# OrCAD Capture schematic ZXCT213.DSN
size C; title: ZXCT213, 26V, ZERO-DRIFT, HIGH PRECISION CURRENT MONITOR; rev: 1.0; note: DS45449 Rev. 2 - 2
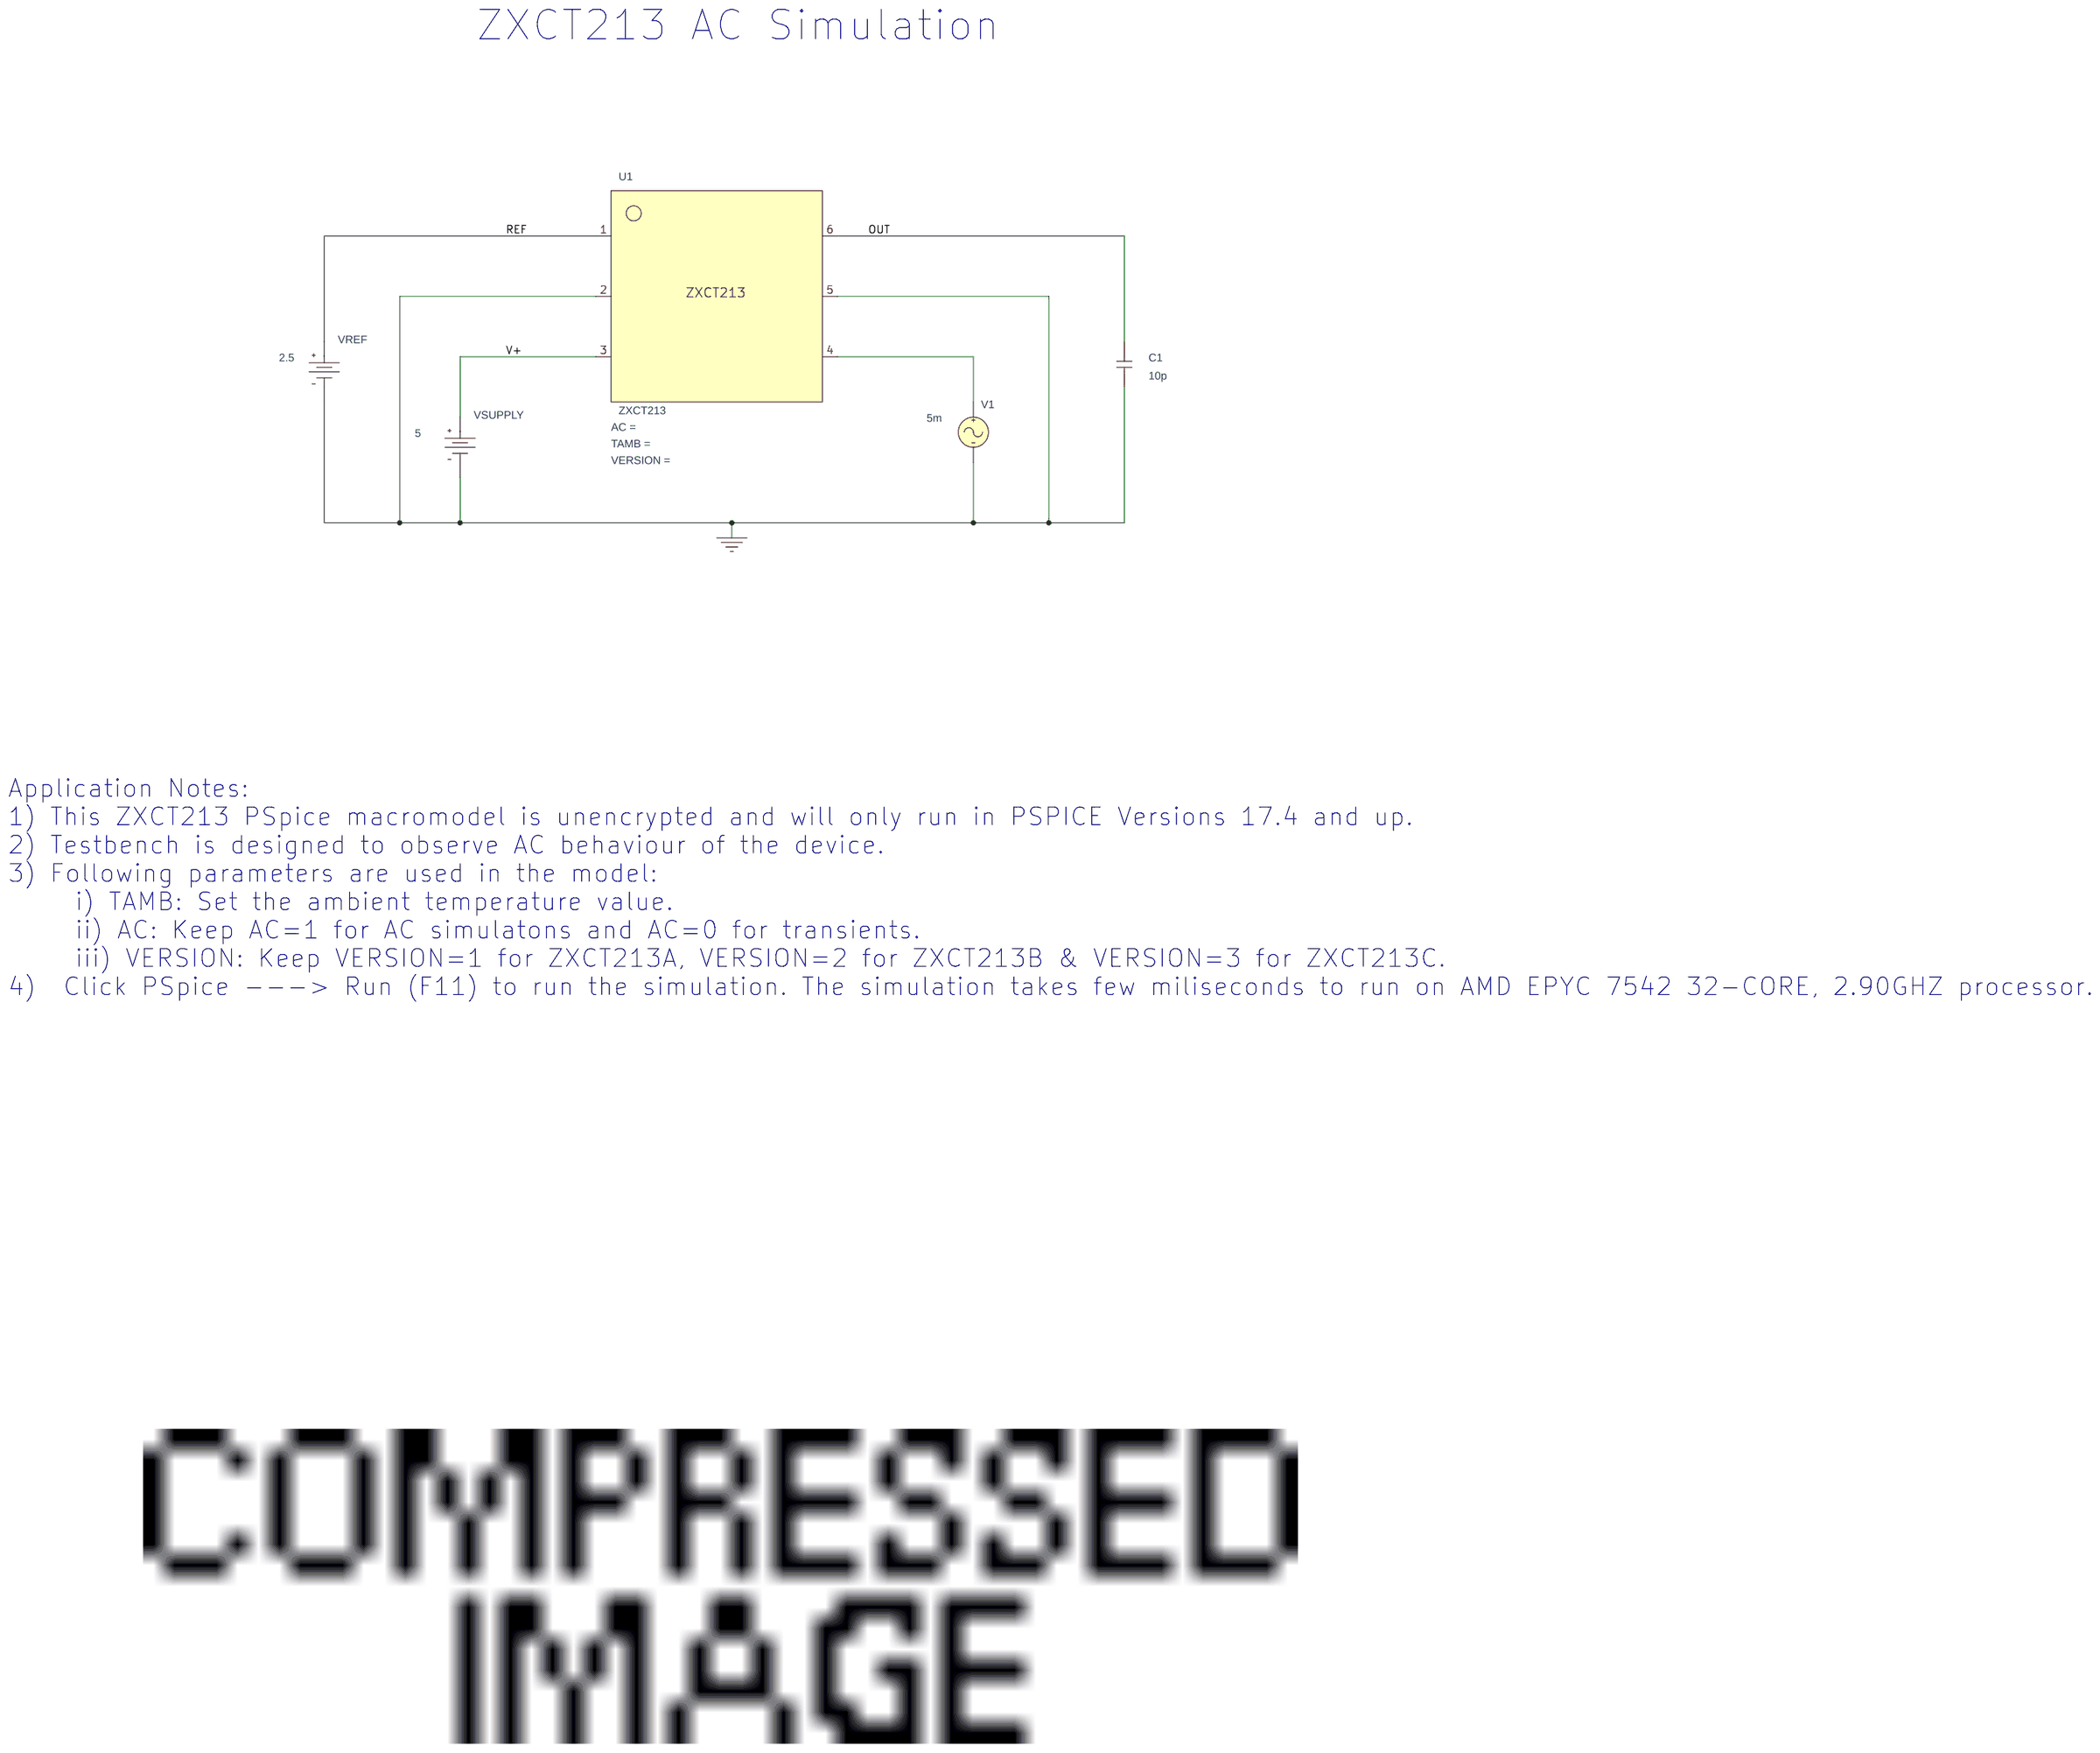
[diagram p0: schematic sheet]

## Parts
C1  10p  [RAD/CK05]
U1  ZXCT213
V1  VAC
VREF  VDC
VSUPPLY  VDC

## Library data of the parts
C1 = C
U1 = ZXCT213
V1 = VAC: ACMAG: 5m
VREF = VDC: DC: 2.5
VSUPPLY = VDC: DC: 5

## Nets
0: C1.2 U1.2(GND) U1.5(IN-) V1.2(-) VREF.1(-) VSUPPLY.1(-)
OUT: C1.1 U1.6(OUT)
REF: U1.1(REF) VREF.0(+)
V+: U1.3(V+) VSUPPLY.0(+)
N16247433: U1.4(IN+) V1.1(+)

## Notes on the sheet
- ZXCT213 AC Simulation
- Application Notes:
  1) This ZXCT213 PSpice macromodel is unencrypted and will only run in PSPICE Versions 17.4 and up.
  2) Testbench is designed to observe AC behaviour of the device.
  3) Following parameters are used in the model:
       i) TAMB: Set the ambient temperature value.
       ii) AC: Keep AC=1 for AC simulatons and AC=0 for transients.
       iii) VERSION: Keep VERSION=1 for ZXCT213A, VERSION=2 for ZXCT213B & VERSION=3 for ZXCT213C.
  4)  Click PSpice ---> Run (F11) to run the simulation. The simulation takes few miliseconds to run on AMD EPYC 7542 32-CORE, 2.90GHZ processor.
